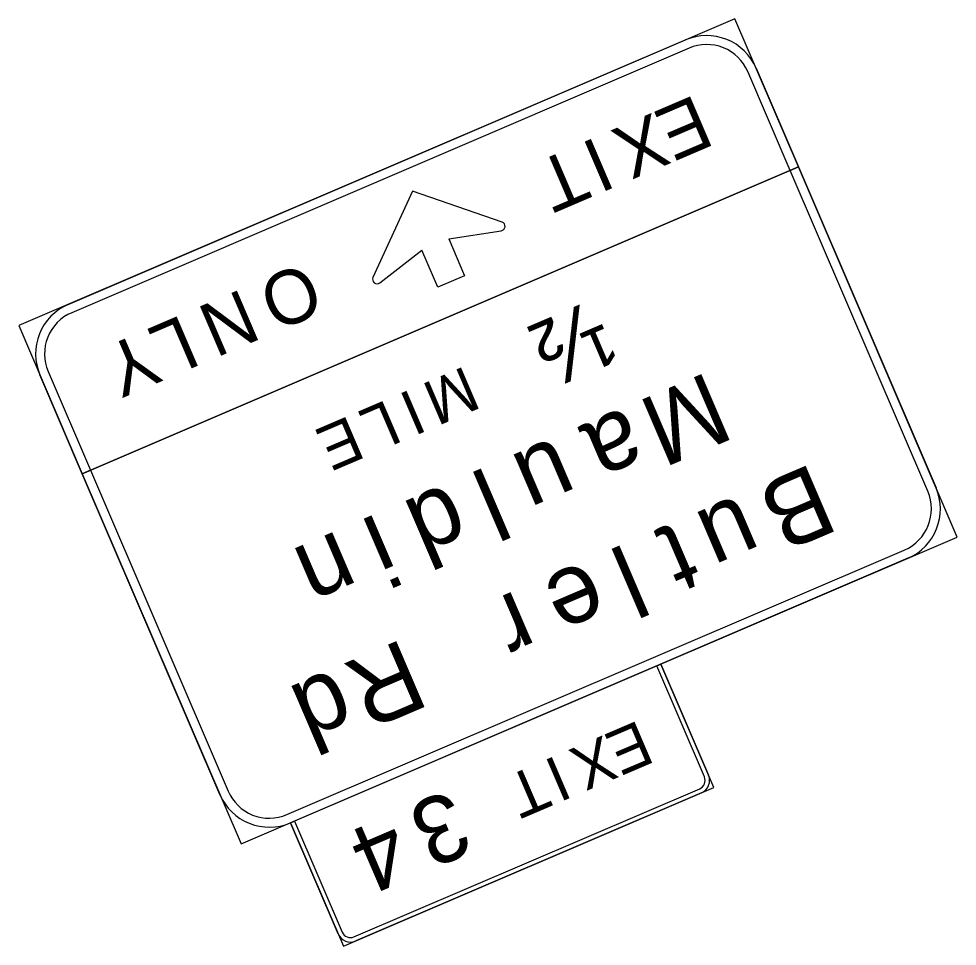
# Model space of a CAD drawing. Extents: x 1581789 to 1622364, y 1043167 to 1103486.
# Drawn here: x 1612659.3 to 1612729.1, y 1087195.3 to 1087264.4 of the extents above; entities that cross this region are included whole.
import ezdxf

# ---------------------------------------------------------------- set-up
doc = ezdxf.new("R2010")
doc.units = 0
doc.layers.add('RD_PD_PatLn2', color=7, linetype='Continuous')

msp = doc.modelspace()

# ---------------------------------------------------------------- linework, layer by layer
at = {"layer": 'RD_PD_PatLn2'}
for points in [[(1612712.571, 1087264.389), (1612659.262, 1087241.537), (1612663.99, 1087230.508), (1612717.299, 1087253.359), (1612712.571, 1087264.389), (1612712.571, 1087264.389)], [(1612662.939, 1087243.113), (1612708.895, 1087262.813)], [(1612709.157, 1087262.2), (1612663.202, 1087242.501)], [(1612716.686, 1087253.097), (1612713.534, 1087260.449)], [(1612714.147, 1087260.712), (1612717.299, 1087253.359), (1612716.686, 1087253.097), (1612716.686, 1087253.097)], [(1612717.299, 1087253.359), (1612663.99, 1087230.508), (1612675.81, 1087202.935), (1612729.119, 1087225.786), (1612717.299, 1087253.359), (1612717.299, 1087253.359)], [(1612726.93, 1087229.2), (1612716.686, 1087253.097), (1612717.299, 1087253.359), (1612727.543, 1087229.462)], [(1612688.56, 1087251.557), (1612685.629, 1087245.126)], [(1612695.238, 1087249.245), (1612688.56, 1087251.557), (1612688.56, 1087251.557)], [(1612691.263, 1087248.001), (1612695.176, 1087248.602)], [(1612691.263, 1087248.001), (1612692.445, 1087245.244), (1612692.445, 1087245.244)], [(1612686.138, 1087244.728), (1612689.272, 1087247.148)], [(1612692.445, 1087245.244), (1612690.454, 1087244.39), (1612689.272, 1087247.148)], [(1612661.451, 1087238.124), (1612664.603, 1087230.771), (1612663.99, 1087230.508), (1612660.838, 1087237.861)], [(1612674.234, 1087206.611), (1612663.99, 1087230.508), (1612664.603, 1087230.771), (1612664.603, 1087230.771)], [(1612664.603, 1087230.771), (1612674.847, 1087206.874)], [(1612679.224, 1087205.123), (1612725.179, 1087224.822)], [(1612725.442, 1087224.21), (1612679.486, 1087204.51)], [(1612707.06, 1087216.33), (1612679.486, 1087204.51), (1612683.426, 1087195.319), (1612711, 1087207.139), (1612707.06, 1087216.33), (1612707.06, 1087216.33)], [(1612710.299, 1087207.927), (1612706.753, 1087216.199), (1612707.06, 1087216.33), (1612710.606, 1087208.058)], [(1612684.214, 1087196.02), (1612709.949, 1087207.051)], [(1612710.08, 1087206.745), (1612684.345, 1087195.713)], [(1612683.032, 1087196.238), (1612679.486, 1087204.51), (1612679.793, 1087204.642), (1612679.793, 1087204.642)], [(1612679.793, 1087204.642), (1612683.339, 1087196.37)]]:
    msp.add_lwpolyline(points, dxfattribs=at)
for centre, radius, start, end in [((1612710.471, 1087259.136), 4, 23.20256, 113.20277), ((1612710.471, 1087259.136), 3.333, 23.20256, 113.20277), ((1612695.126, 1087248.932), 0.333, 278.73001, 70.17765), ((1612685.934, 1087244.992), 0.333, 156.22789, 307.67553), ((1612664.515, 1087239.437), 4, 113.20277, 203.20298), ((1612664.515, 1087239.437), 3.333, 113.20277, 203.20298), ((1612723.866, 1087227.886), 4, 293.20292, 23.20256), ((1612723.866, 1087227.886), 3.333, 293.20292, 23.20256), ((1612709.687, 1087207.664), 0.667, 293.20292, 23.20256), ((1612709.687, 1087207.664), 1, 293.20292, 23.20256), ((1612677.91, 1087208.187), 4, 203.20271, 293.20292), ((1612677.91, 1087208.187), 3.333, 203.20271, 293.20292), ((1612683.951, 1087196.632), 1, 203.20271, 293.20292), ((1612683.951, 1087196.632), 0.667, 203.20271, 293.20292)]:
    msp.add_arc(centre, radius, start, end, dxfattribs=at)

# ---------------------------------------------------------------- texts
for s, height, p in [('E', 4, (1612709.635, 1087258.778)), ('X', 4, (1612706.477, 1087257.424)), ('I', 4, (1612702.302, 1087255.635)), ('T', 4, (1612700.475, 1087254.851)), ('O', 4, (1612680.638, 1087246.348)), ('N', 4, (1612675.902, 1087244.318)), ('½', 5, (1612702.056, 1087243.561)), ('L', 4, (1612671.416, 1087242.395)), ('Y', 4, (1612668.57, 1087241.175)), ('M', 3.333, (1612692.519, 1087238.566)), ('M', 5.333, (1612710.605, 1087238.159)), ('I', 3.333, (1612688.503, 1087236.845)), ('L', 3.333, (1612686.668, 1087236.059)), ('a', 5.333, (1612704.484, 1087235.535)), ('E', 3.333, (1612683.899, 1087234.871)), ('u', 5.333, (1612699.306, 1087233.316)), ('l', 5.333, (1612694.099, 1087231.084)), ('B', 5.333, (1612718.371, 1087231.333)), ('d', 5.333, (1612691.274, 1087229.873)), ('u', 5.333, (1612712.998, 1087229.03)), ('i', 5.333, (1612685.957, 1087227.593)), ('t', 5.333, (1612708.29, 1087227.012)), ('n', 5.333, (1612683.049, 1087226.347)), ('l', 5.333, (1612704.413, 1087225.35)), ('e', 5.333, (1612701.588, 1087224.139)), ('r', 5.333, (1612696.326, 1087221.883)), ('R', 5.333, (1612687.899, 1087218.272)), ('d', 5.333, (1612682.776, 1087216.075)), ('E', 3.333, (1612705.432, 1087212.187)), ('X', 3.333, (1612702.801, 1087211.059)), ('I', 3.333, (1612699.322, 1087209.568)), ('T', 3.333, (1612697.799, 1087208.915)), ('3', 5, (1612691.408, 1087207.082)), ('4', 5, (1612686.916, 1087205.157))]:
    msp.add_text(s, height=height, rotation=203.20271, dxfattribs=at).set_placement(p)

doc.saveas('drawing.dxf')
